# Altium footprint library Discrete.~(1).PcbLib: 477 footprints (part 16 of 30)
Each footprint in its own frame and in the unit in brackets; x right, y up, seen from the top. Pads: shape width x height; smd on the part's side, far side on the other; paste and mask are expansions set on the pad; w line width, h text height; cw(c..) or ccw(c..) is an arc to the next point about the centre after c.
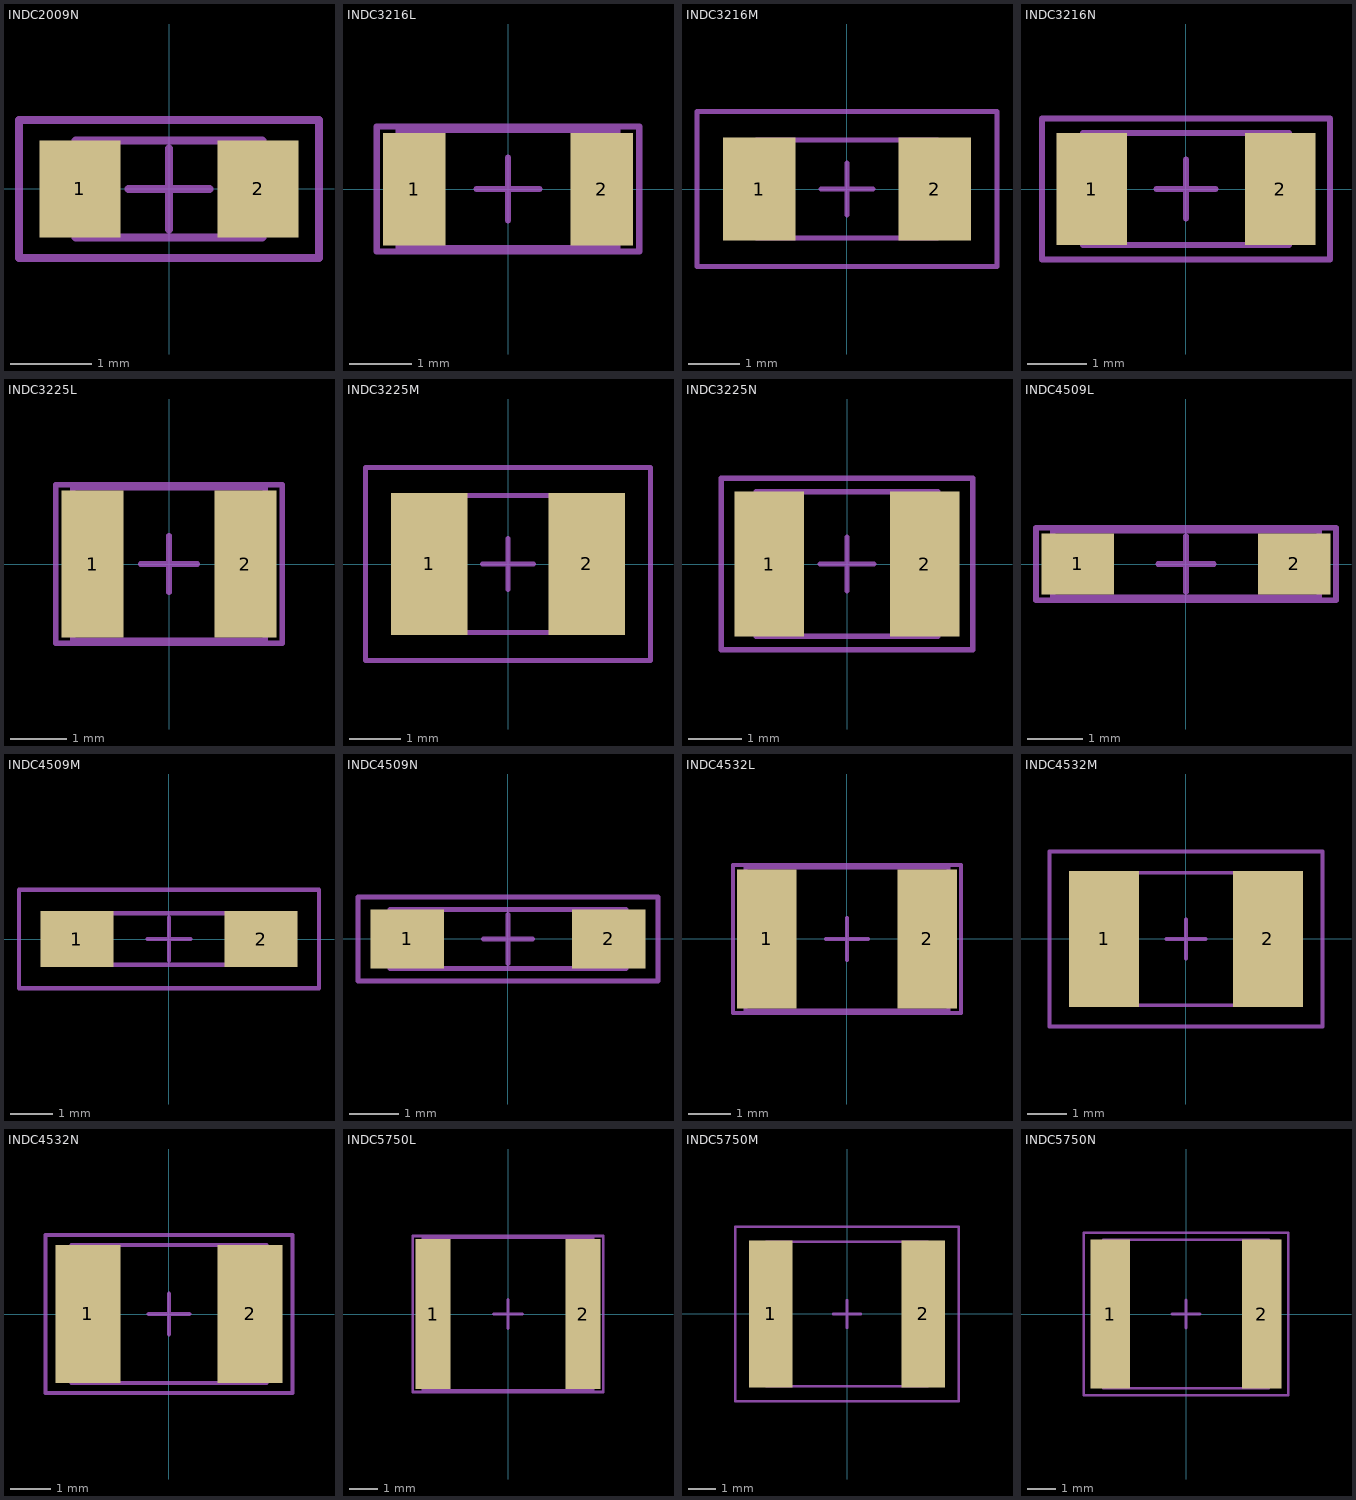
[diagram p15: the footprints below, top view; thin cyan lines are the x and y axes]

## INDC2009N [mm] "Chip Inductor, Body 2.0x0.9mm, IPC Medium Density"
height 1.2
pads (2):
  rect 1x1.2 smd: 1(-1.1,0) 2(1.1,0)
Mechanical 13:
  lines w0.1: -1.15,-0.6 1.15,-0.6 1.15,0.6 -1.15,0.6 -1.15,-0.6
Mechanical 15:
  lines w0.1: -0.5,0 0.5,0 ; 0,-0.5 0,0.5 ; -1.85,-0.85 1.85,-0.85 1.85,0.85 -1.85,0.85 -1.85,-0.85
3D body: height 1.2, standoff 0, extent -1.15,-0.6 1.15,0.6

## INDC3216L [mm] "Chip Inductor, Body 3.2x1.6mm, IPC High Density"
height 1.9
pads (2):
  rect 1x1.8 smd: 1(-1.5,0) 2(1.5,0)
Mechanical 13:
  lines w0.1: -1.75,-0.95 1.75,-0.95 1.75,0.95 -1.75,0.95 -1.75,-0.95
Mechanical 15:
  lines w0.1: -0.5,0 0.5,0 ; 0,-0.5 0,0.5 ; -2.1,-1 2.1,-1 2.1,1 -2.1,1 -2.1,-1
3D body: height 1.9, standoff 0, extent -1.75,-0.95 1.75,0.95

## INDC3216M [mm] "Chip Inductor, Body 3.2x1.6mm, IPC Low Density"
height 1.9
pads (2):
  rect 1.4x2 smd: 1(-1.7,0) 2(1.7,0)
Mechanical 13:
  lines w0.1: -1.75,-0.95 -1.75,0.95 1.75,0.95 1.75,-0.95 -1.75,-0.95
Mechanical 15:
  lines w0.1: -0.5,0 0.5,0 ; 0,-0.5 0,0.5 ; -2.9,-1.5 -2.9,1.5 2.9,1.5 2.9,-1.5 -2.9,-1.5
3D body: height 1.9, standoff 0, extent -1.75,-0.95 1.75,0.95

## INDC3216N [mm] "Chip Inductor, Body 3.2x1.6mm, IPC Medium Density"
height 1.9
pads (2):
  rect 1.2x1.9 smd: 1(-1.6,0) 2(1.6,0)
Mechanical 13:
  lines w0.1: -1.75,-0.95 1.75,-0.95 1.75,0.95 -1.75,0.95 -1.75,-0.95
Mechanical 15:
  lines w0.1: -0.5,0 0.5,0 ; 0,-0.5 0,0.5 ; -2.45,-1.2 2.45,-1.2 2.45,1.2 -2.45,1.2 -2.45,-1.2
3D body: height 1.9, standoff 0, extent -1.75,-0.95 1.75,0.95

## INDC3225L [mm] "Chip Inductor, Body 3.2x2.5mm, IPC High Density"
height 1.5
pads (2):
  rect 1.1x2.6 smd: 1(-1.35,0) 2(1.35,0)
Mechanical 13:
  lines w0.1: -1.7,-1.35 1.7,-1.35 1.7,1.35 -1.7,1.35 -1.7,-1.35
Mechanical 15:
  lines w0.1: -0.5,0 0.5,0 ; 0,-0.5 0,0.5 ; -2,-1.4 2,-1.4 2,1.4 -2,1.4 -2,-1.4
3D body: height 1.5, standoff 0, extent -1.7,-1.35 1.7,1.35

## INDC3225M [mm] "Chip Inductor, Body 3.2x2.5mm, IPC Low Density"
height 1.5
pads (2):
  rect 1.5x2.8 smd: 1(-1.55,0) 2(1.55,0)
Mechanical 13:
  lines w0.1: -1.7,-1.35 1.7,-1.35 1.7,1.35 -1.7,1.35 -1.7,-1.35
Mechanical 15:
  lines w0.1: -0.5,0 0.5,0 ; 0,-0.5 0,0.5 ; -2.8,-1.9 2.8,-1.9 2.8,1.9 -2.8,1.9 -2.8,-1.9
3D body: height 1.5, standoff 0, extent -1.7,-1.35 1.7,1.35

## INDC3225N [mm] "Chip Inductor, Body 3.2x2.5mm, IPC Medium Density"
height 1.5
pads (2):
  rect 1.3x2.7 smd: 1(-1.45,0) 2(1.45,0)
Mechanical 13:
  lines w0.1: -1.7,-1.35 1.7,-1.35 1.7,1.35 -1.7,1.35 -1.7,-1.35
Mechanical 15:
  lines w0.1: -0.5,0 0.5,0 ; 0,-0.5 0,0.5 ; -2.35,-1.6 2.35,-1.6 2.35,1.6 -2.35,1.6 -2.35,-1.6
3D body: height 1.5, standoff 0, extent -1.7,-1.35 1.7,1.35

## INDC4509L [mm] "Chip Inductor, Body 4.5x0.9mm, IPC High Density"
height 1.9
pads (2):
  rect 1.3x1.1 smd: 1(-1.95,0) 2(1.95,0)
Mechanical 13:
  lines w0.1: -2.4,-0.6 -2.4,0.6 2.4,0.6 2.4,-0.6 -2.4,-0.6
Mechanical 15:
  lines w0.1: -0.5,0 0.5,0 ; 0,-0.5 0,0.5 ; -2.7,-0.65 -2.7,0.65 2.7,0.65 2.7,-0.65 -2.7,-0.65
3D body: height 1.9, standoff 0, extent -2.4,-0.6 2.4,0.6

## INDC4509M [mm] "Chip Inductor, Body 4.5x0.9mm, IPC Low Density"
height 1.9
pads (2):
  rect 1.7x1.3 smd: 1(-2.15,0) 2(2.15,0)
Mechanical 13:
  lines w0.1: -2.4,-0.6 2.4,-0.6 2.4,0.6 -2.4,0.6 -2.4,-0.6
Mechanical 15:
  lines w0.1: -0.5,0 0.5,0 ; 0,-0.5 0,0.5 ; -3.5,-1.15 3.5,-1.15 3.5,1.15 -3.5,1.15 -3.5,-1.15
3D body: height 1.9, standoff 0, extent -2.4,-0.6 2.4,0.6

## INDC4509N [mm] "Chip Inductor, Body 4.5x0.9mm, IPC Medium Density"
height 1.9
pads (2):
  rect 1.5x1.2 smd: 1(-2.05,0) 2(2.05,0)
Mechanical 13:
  lines w0.1: -2.4,-0.6 2.4,-0.6 2.4,0.6 -2.4,0.6 -2.4,-0.6
Mechanical 15:
  lines w0.1: -0.5,0 0.5,0 ; 0,-0.5 0,0.5 ; -3.05,-0.85 3.05,-0.85 3.05,0.85 -3.05,0.85 -3.05,-0.85
3D body: height 1.9, standoff 0, extent -2.4,-0.6 2.4,0.6

## INDC4532L [mm] "Chip Inductor, Body 4.5x3.2mm, IPC High Density"
height 1.35
pads (2):
  rect 1.4x3.3 smd: 1(-1.9,0) 2(1.9,0)
Mechanical 13:
  lines w0.1: -2.4,-1.7 -2.4,1.7 2.4,1.7 2.4,-1.7 -2.4,-1.7
Mechanical 15:
  lines w0.1: -0.5,0 0.5,0 ; 0,-0.5 0,0.5 ; -2.7,-1.75 -2.7,1.75 2.7,1.75 2.7,-1.75 -2.7,-1.75
3D body: height 1.35, standoff 0, extent -2.4,-1.7 2.4,1.7

## INDC4532M [mm] "Chip Inductor, Body 4.5x3.2mm, IPC Low Density"
height 1.35
pads (2):
  rect 1.8x3.5 smd: 1(-2.1,0) 2(2.1,0)
Mechanical 13:
  lines w0.1: -2.4,-1.7 2.4,-1.7 2.4,1.7 -2.4,1.7 -2.4,-1.7
Mechanical 15:
  lines w0.1: -0.5,0 0.5,0 ; 0,-0.5 0,0.5 ; -3.5,-2.25 3.5,-2.25 3.5,2.25 -3.5,2.25 -3.5,-2.25
3D body: height 1.35, standoff 0, extent -2.4,-1.7 2.4,1.7

## INDC4532N [mm] "Chip Inductor, Body 4.5x3.2mm, IPC Medium Density"
height 1.35
pads (2):
  rect 1.6x3.4 smd: 1(-2,0) 2(2,0)
Mechanical 13:
  lines w0.1: -2.4,-1.7 -2.4,1.7 2.4,1.7 2.4,-1.7 -2.4,-1.7
Mechanical 15:
  lines w0.1: -0.5,0 0.5,0 ; 0,-0.5 0,0.5 ; -3.05,-1.95 -3.05,1.95 3.05,1.95 3.05,-1.95 -3.05,-1.95
3D body: height 1.35, standoff 0, extent -2.4,-1.7 2.4,1.7

## INDC5750L [mm] "Chip Inductor, Body 5.7x5.0mm, IPC High Density"
height 1.9
pads (2):
  rect 1.2x5.2 smd: 1(-2.6,0) 2(2.6,0)
Mechanical 13:
  lines w0.1: -2.95,-2.65 2.95,-2.65 2.95,2.65 -2.95,2.65 -2.95,-2.65
Mechanical 15:
  lines w0.1: -0.5,0 0.5,0 ; 0,-0.5 0,0.5 ; -3.3,-2.7 3.3,-2.7 3.3,2.7 -3.3,2.7 -3.3,-2.7
3D body: height 1.9, standoff 0, extent -2.95,-2.65 2.95,2.65

## INDC5750M [mm] "Chip Inductor, Body 5.7x5.0mm, IPC Low Density"
height 1.9
pads (2):
  rect 1.6x5.4 smd: 1(-2.8,0) 2(2.8,0)
Mechanical 13:
  lines w0.1: -2.95,-2.65 -2.95,2.65 2.95,2.65 2.95,-2.65 -2.95,-2.65
Mechanical 15:
  lines w0.1: -0.5,0 0.5,0 ; 0,-0.5 0,0.5 ; -4.1,-3.2 -4.1,3.2 4.1,3.2 4.1,-3.2 -4.1,-3.2
3D body: height 1.9, standoff 0, extent -2.95,-2.65 2.95,2.65

## INDC5750N [mm] "Chip Inductor, Body 5.7x5.0mm, IPC Medium Density"
height 1.9
pads (2):
  rect 1.4x5.3 smd: 1(-2.7,0) 2(2.7,0)
Mechanical 13:
  lines w0.1: -2.95,-2.65 -2.95,2.65 2.95,2.65 2.95,-2.65 -2.95,-2.65
Mechanical 15:
  lines w0.1: -0.5,0 0.5,0 ; 0,-0.5 0,0.5 ; -3.65,-2.9 -3.65,2.9 3.65,2.9 3.65,-2.9 -3.65,-2.9
3D body: height 1.9, standoff 0, extent -2.95,-2.65 2.95,2.65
